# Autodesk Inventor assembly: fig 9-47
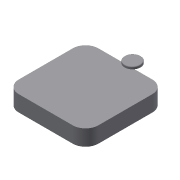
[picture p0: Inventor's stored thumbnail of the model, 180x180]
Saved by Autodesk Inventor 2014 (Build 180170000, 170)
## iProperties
Created: 2013-07
Part Number: fig 9-47
Document SubType Name: Assembly
Designer: CADCIM
Author: CADCIM
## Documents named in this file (3)
- E:\APS\Autodesk Inventor 2014-Project\inventor_2014_partfiles\Inventor_2014_prt\c09_Inv_2014_prt\c09_inv_2014_prt\fig 9-47.iam
- E:\APS\c09partfile\fig 9-47_1.ipt
- E:\APS\c09partfile\fig 9-47_2.ipt
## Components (2 placed, 2 different names)
1. fig 9-47_1:1
2. fig 9-47_2:1
